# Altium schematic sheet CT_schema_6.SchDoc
size 371 x 335 mm
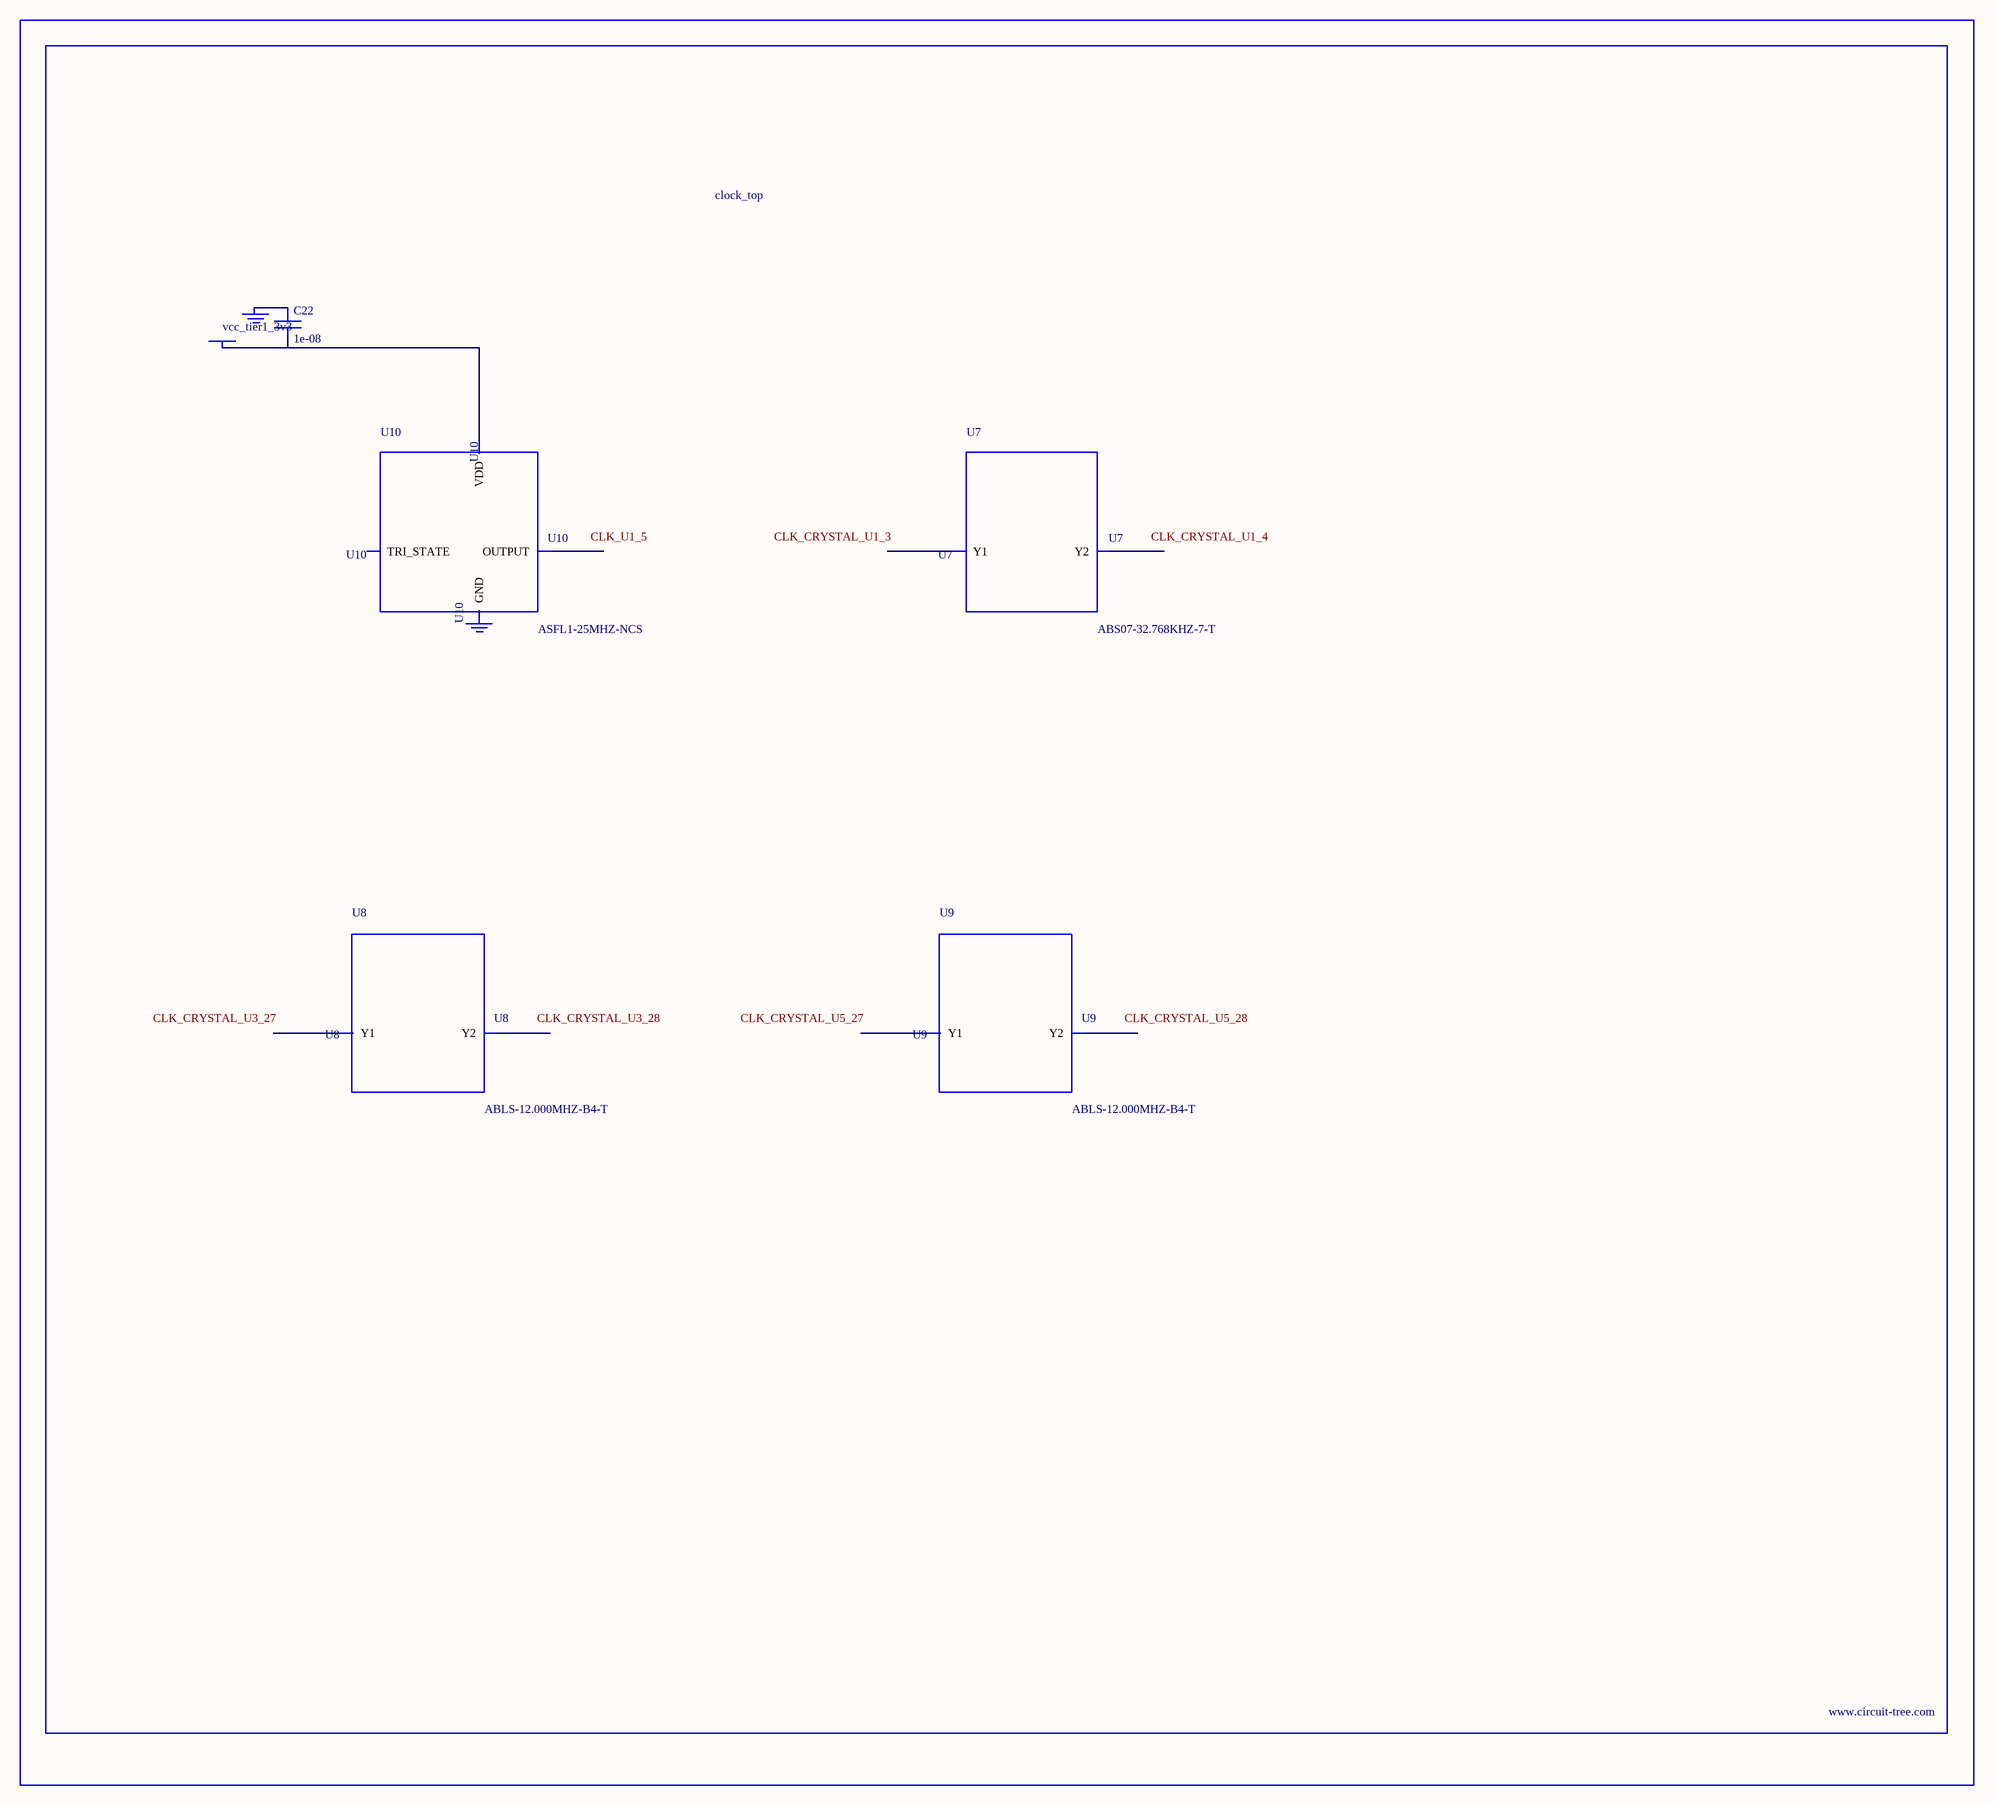
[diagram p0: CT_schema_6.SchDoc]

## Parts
BORDER5  (no value)
C22  1e-08  [C0402]
GND_INSTANCE_5_0  (no value)
GND_INSTANCE_5_1  (no value)
POWER_INSTANCE_5_0  vcc_tier1_3v3
U7  ABS07-32.768KHZ-7-T  [ABS07-32.768KHZ-7-T]
U8  ABLS-12.000MHZ-B4-T  [ABLS-12.000MHZ-B4-T]
U9  ABLS-12.000MHZ-B4-T  [ABLS-12.000MHZ-B4-T]
U10  ASFL1-25MHZ-NCS  [ASFL1]

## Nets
NetC22_1: C22.1 GND_INSTANCE_5_0.0(GND)
NetC22_2: C22.2 POWER_INSTANCE_5_0.0(PWR) U10.4(VDD)

Not connected (* = marked no-connect by the designer): GND_INSTANCE_5_1 0(GND); U7 1(Y1) 2(Y2); U8 1(Y1) 2(Y2); U9 1(Y1) 2(Y2); U10 1(TRI_STATE) 2(GND) 3(OUTPUT)

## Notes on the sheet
- Labels drawn without touching a wire or pin: CLK_CRYSTAL_U1_3, CLK_CRYSTAL_U1_4, CLK_CRYSTAL_U3_27, CLK_CRYSTAL_U3_28, CLK_CRYSTAL_U5_27, CLK_CRYSTAL_U5_28, CLK_U1_5

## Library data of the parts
BORDER5 = BORDER_PAGE5
C22 = C0402C103K3RAC
GND_INSTANCE_5_0 GND_INSTANCE_5_1 = GND
POWER_INSTANCE_5_0 = PWR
